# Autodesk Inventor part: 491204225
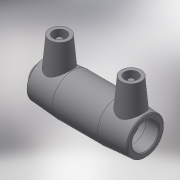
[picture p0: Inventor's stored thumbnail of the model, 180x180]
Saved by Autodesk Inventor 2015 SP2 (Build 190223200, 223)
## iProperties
Created: 2017-06
Part Number: 491204225
Material: Generic
Description: PLASSON END CAP 225
Document SubType Name: Modeling
Designer: KIM
Mass: 38.9236 g
Surface Area: 152.394 cm^2
Volume: 38.9236 cm^3
Density: 1 g/cm^3
Appearance: Default
Author: KIM
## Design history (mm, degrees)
derived "491204.ipt"
feature "Solid1::491204.ipt"
tag "TaggingFeature1"
body "Solid1"
other parameters: "d1" = 225, "d2" = 272, "d3" = 119, "d4" = 79.5, "d5" = 244.8, "d6" = 213.75, "d7" = 225, "d8" = 168 deg, "d10" = 47.6, "d11" = 15.86667, "d13" = 254.4, "d14" = 17.6296, "d15" = 119, "d16" = 119, "d17" = 213.75, "d18" = 225, "d19" = 3.52592, "d20" = 168 deg, "d22" = 255.68, "d23" = 272, "d24" = 248.0096, "d25" = 135 deg, "d26" = 114.48, "d27" = 135 deg, "d29" = 138, "d30" = 15, "d31" = 101.76, "d34" = 5 deg, "d35" = 15, "d39" = 5 deg, "d41" = 4, "d42" = 14, "d43" = 0, "d45" = 4, "d46" = 14, "d47" = 0, "d48" = 318, "d49" = 1, "d52" = 5.724, "d53" = 247.5, "d54" = 5.724, "d56" = 22.5, "d57" = 6.75, "d60" = 47.7, "d61" = 4.5, "d63" = 318, "d64" = 1, "d67" = 45, "d68" = 247.5, "d69" = 6.36, "d70" = 0, "d71" = 5.724, "d72" = 3, "d73" = 0, "d74" = 34.51, "d75" = 11.50333, "d76" = 3, "d77" = 0, "d_" = 225, "L_" = 318, "L_1" = 119, "D_" = 272, "A_" = 138, "d_2" = 12, "d55" = 22.5
